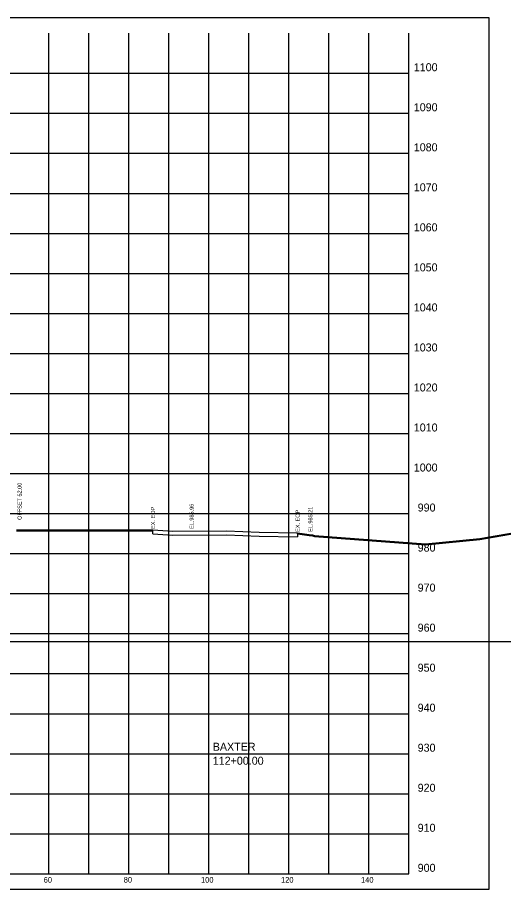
# Model space of a CAD drawing. Extents: x 5868 to 6683, y 2883 to 19120.
# Drawn here: x 6246 to 6367.5, y 14883.1 to 15101 of the extents above; entities that cross this region are included whole.
import ezdxf

# ---------------------------------------------------------------- set-up
doc = ezdxf.new("R2010")
doc.units = 0
for name, color, linetype in [('DESIGN - SHEET - Corner Text', 7, 'Continuous'), ('DESIGN - SHEET - Light Grid', 7, 'Continuous'), ('DESIGN - SHEET - Linework', 7, 'Continuous'), ('DESIGN - SHEET - Plot Shape', 7, 'Continuous'), ('DESIGN - TYPICAL - Slope Tie Text', 7, 'Continuous'), ('DESIGN - TYPICAL - Warning Text', 7, 'Continuous'), ('SURVEY - GROUND - Bottom of Topsoil Layer', 7, 'Continuous'), ('SURVEY - GROUND - Existing Pavement Layer', 7, 'Continuous'), ('SURVEY - GROUND - Existing Pavement Text', 7, 'Continuous'), ('SURVEY - GROUND - Top of Ground', 7, 'Continuous')]:
    doc.layers.add(name, color=color, linetype=linetype)

msp = doc.modelspace()

# ---------------------------------------------------------------- linework, layer by layer
at = {"layer": 'DESIGN - SHEET - Light Grid'}
msp.add_line((6193.78, 14945.07), (6493.78, 14945.07), dxfattribs=at)
at = {"layer": 'DESIGN - SHEET - Linework'}
for p, q in [((6253.78, 14887.07), (6253.78, 15097.07)), ((6263.78, 14887.07), (6263.78, 15097.07)), ((6273.78, 14887.07), (6273.78, 15097.07)), ((6283.78, 14887.07), (6283.78, 15097.07)), ((6293.78, 14887.07), (6293.78, 15097.07)), ((6303.78, 14887.07), (6303.78, 15097.07)), ((6313.78, 14887.07), (6313.78, 15097.07)), ((6323.78, 14887.07), (6323.78, 15097.07)), ((6333.78, 14887.07), (6333.78, 15097.07)), ((6043.78, 15087.07), (6343.78, 15087.07)), ((6043.78, 15077.07), (6343.78, 15077.07)), ((6043.78, 15067.07), (6343.78, 15067.07)), ((6043.78, 15057.07), (6343.78, 15057.07)), ((6043.78, 15047.07), (6343.78, 15047.07)), ((6043.78, 15037.07), (6343.78, 15037.07)), ((6043.78, 15027.07), (6343.78, 15027.07)), ((6043.78, 15017.07), (6343.78, 15017.07)), ((6043.78, 15007.07), (6343.78, 15007.07)), ((6043.78, 14997.07), (6343.78, 14997.07)), ((6043.78, 14987.07), (6343.78, 14987.07)), ((6043.78, 14977.07), (6343.78, 14977.07)), ((6043.78, 14967.07), (6343.78, 14967.07)), ((6043.78, 14957.07), (6343.78, 14957.07)), ((6043.78, 14947.07), (6343.78, 14947.07)), ((6043.78, 14937.07), (6343.78, 14937.07)), ((6043.78, 14927.07), (6343.78, 14927.07)), ((6043.78, 14917.07), (6343.78, 14917.07)), ((6043.78, 14907.07), (6343.78, 14907.07)), ((6043.78, 14897.07), (6343.78, 14897.07))]:
    msp.add_line(p, q, dxfattribs=at)
msp.add_lwpolyline([(6043.78, 15097.07), (6043.78, 14887.07), (6343.78, 14887.07), (6343.78, 15097.07)], dxfattribs=at)
at = {"layer": 'DESIGN - SHEET - Plot Shape'}
msp.add_lwpolyline([(6023.78, 15101.01), (6363.78, 15101.01), (6363.78, 14883.13), (6023.78, 14883.13)], close=True, dxfattribs=at)
at = {"layer": 'SURVEY - GROUND - Bottom of Topsoil Layer'}
for p, q in [((6245.69, 14972.73), (6260.83, 14972.72)), ((6260.83, 14972.72), (6263.17, 14972.75)), ((6263.17, 14972.75), (6279.76, 14972.78)), ((6279.76, 14972.78), (6279.83, 14972.78)), ((6279.83, 14972.78), (6279.83, 14973.03)), ((6361.53, 14970.57), (6379.4, 14973.71)), ((6315.99, 14972.04), (6315.99, 14972.29)), ((6315.99, 14972.04), (6318.84, 14971.57)), ((6318.84, 14971.57), (6319.75, 14971.47)), ((6319.75, 14971.47), (6320.23, 14971.34)), ((6320.23, 14971.34), (6347.96, 14969.27)), ((6347.96, 14969.27), (6361.53, 14970.57))]:
    msp.add_line(p, q, dxfattribs=at)
at = {"layer": 'SURVEY - GROUND - Existing Pavement Layer'}
for p, q in [((6279.83, 14972.03), (6279.83, 14973.03)), ((6279.83, 14972.03), (6284.78, 14971.71)), ((6284.78, 14971.71), (6298.18, 14971.76)), ((6298.18, 14971.76), (6306.41, 14971.43)), ((6306.41, 14971.43), (6315.99, 14971.29)), ((6315.99, 14972.29), (6315.99, 14971.29))]:
    msp.add_line(p, q, dxfattribs=at)
at = {"layer": 'SURVEY - GROUND - Top of Ground'}
msp.add_lwpolyline([(6245.69, 14972.98), (6260.83, 14972.97), (6263.17, 14973), (6279.76, 14973.03), (6284.78, 14972.71), (6298.18, 14972.76), (6306.41, 14972.43), (6315.99, 14972.29), (6318.84, 14971.82), (6319.75, 14971.72), (6320.23, 14971.59), (6347.96, 14969.52), (6361.53, 14970.82), (6379.4, 14973.96)], dxfattribs=at)

# ---------------------------------------------------------------- texts
at = {"layer": 'DESIGN - SHEET - Corner Text'}
for s, height, p in [('1100', 2, (6345.03, 15087.57)), ('1090', 2, (6345.03, 15077.57)), ('1080', 2, (6345.03, 15067.57)), ('1070', 2, (6345.03, 15057.57)), ('1060', 2, (6345.03, 15047.57)), ('1050', 2, (6345.03, 15037.57)), ('1040', 2, (6345.03, 15027.57)), ('1030', 2, (6345.03, 15017.57)), ('1020', 2, (6345.03, 15007.57)), ('1010', 2, (6345.03, 14997.57)), ('1000', 2, (6345.03, 14987.57)), ('990', 2, (6346, 14977.57)), ('980', 2, (6346, 14967.57)), ('970', 2, (6346, 14957.57)), ('960', 2, (6346, 14947.57)), ('950', 2, (6346, 14937.57)), ('940', 2, (6346, 14927.57)), ('930', 2, (6346, 14917.57)), ('920', 2, (6346, 14907.57)), ('910', 2, (6346, 14897.57)), ('900', 2, (6346, 14887.57)), ('60', 1.4, (6252.52, 14884.87)), ('80', 1.4, (6272.52, 14884.87)), ('100', 1.4, (6291.84, 14884.87)), ('120', 1.4, (6311.84, 14884.87)), ('140', 1.4, (6331.84, 14884.87))]:
    msp.add_text(s, height=height, dxfattribs=at).set_placement(p)
at = {"layer": 'DESIGN - TYPICAL - Slope Tie Text'}
msp.add_text('OFFSET 52.00', height=1, rotation=90, dxfattribs=at).set_placement((6246.98, 14975.49))
at = {"layer": 'DESIGN - TYPICAL - Warning Text'}
for s, p in [('BAXTER', (6294.78, 14917.82)), ('112+00.00', (6294.78, 14914.32))]:
    msp.add_text(s, height=2, dxfattribs=at).set_placement(p)
at = {"layer": 'SURVEY - GROUND - Existing Pavement Text'}
for s, p in [('EL.985.96', (6290, 14973.23)), ('EX. EOP', (6280.33, 14973.23)), ('EX. EOP', (6316.49, 14972.49)), ('EL.985.21', (6319.68, 14972.49))]:
    msp.add_text(s, height=1, rotation=90, dxfattribs=at).set_placement(p)

doc.saveas('drawing.dxf')
